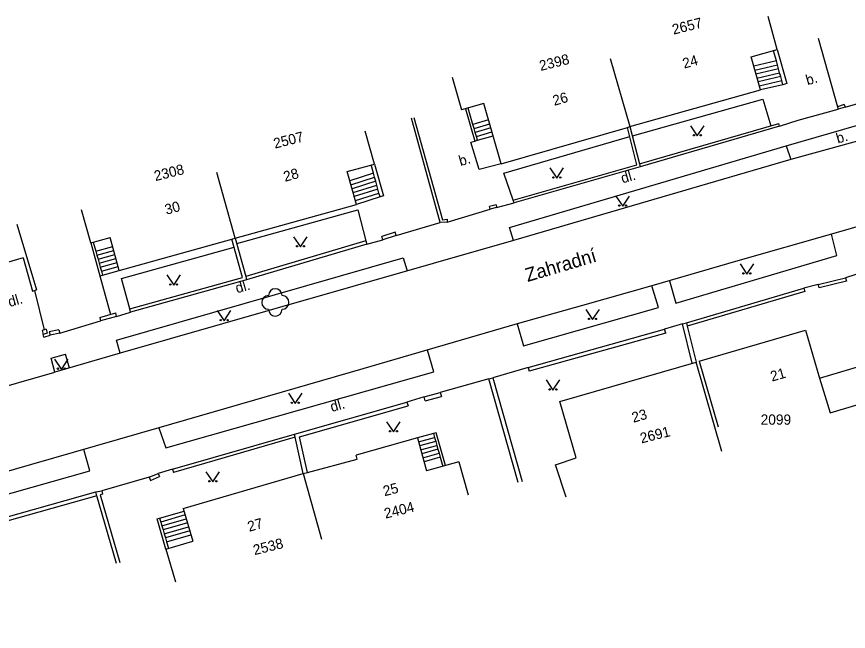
# Model space of a CAD drawing. Extents: x -584400 to -581602, y -1210894 to -1208793.
# Drawn here: x -583100 to -583039.1, y -1209753.8 to -1209708.8 of the extents above; entities that cross this region are included whole.
import ezdxf

# ---------------------------------------------------------------- set-up
doc = ezdxf.new("R2010")
doc.units = 0
for name, color, linetype in [('BUDOVY_MĚŘ', 7, 'Continuous'), ('NÁZVY_ULIC_TOK_SMĚR', 7, 'Continuous'), ('POMOC_POPIS', 7, 'Continuous'), ('ROZHRANÍ_PLOCH', 7, 'Continuous'), ('ZELEŇ', 7, 'Continuous'), ('ZN_DOPLŇKOVÉ', 7, 'Continuous'), ('ZN_KULTUR', 7, 'Continuous'), ('Č_POPIS_EVID', 7, 'Continuous')]:
    doc.layers.add(name, color=color, linetype=linetype)

msp = doc.modelspace()

# ---------------------------------------------------------------- linework, layer by layer
at = {"layer": 'BUDOVY_MĚŘ'}
for points in [[(-583055.11, -1209716.85), (-583045.56, -1209714.16), (-583046.24, -1209711.75), (-583044.32, -1209711.21), (-583044.99, -1209708.8)], [(-583056.55, -1209711.86), (-583055.11, -1209716.85)], [(-583068.14, -1209713.22), (-583067.44, -1209715.62)], [(-583064.53, -1209719.58), (-583065.82, -1209715.15), (-583067.44, -1209715.62)], [(-583064.53, -1209719.58), (-583055.3, -1209716.9), (-583055.11, -1209716.85)], [(-583084.02, -1209725.02), (-583075.14, -1209722.55), (-583075.81, -1209720.14), (-583073.82, -1209719.59), (-583074.49, -1209717.18)], [(-583084.02, -1209725.02), (-583085.36, -1209720.2)], [(-583094.6, -1209725.35), (-583095.27, -1209722.94)], [(-583100.01, -1209723.99), (-583098.56, -1209728.78)], [(-583094.6, -1209725.35), (-583093.18, -1209724.96)], [(-583092.51, -1209727.37), (-583093.18, -1209724.96)], [(-583092.51, -1209727.37), (-583084.26, -1209725.09), (-583084.02, -1209725.02)], [(-583099.55, -1209726.46), (-583104.8, -1209727.98)], [(-583099.55, -1209726.46), (-583098.87, -1209728.88), (-583098.71, -1209728.83), (-583098.56, -1209728.78)], [(-583050.05, -1209734.01), (-583042.26, -1209731.75), (-583041.22, -1209735.26)], [(-583050.05, -1209734.01), (-583048.66, -1209738.81)], [(-583059.77, -1209743.97), (-583060.57, -1209741.6), (-583059.06, -1209741.09), (-583060.24, -1209736.95), (-583050.26, -1209734.08)], [(-583048.38, -1209740.62), (-583050.26, -1209734.08)], [(-583041.22, -1209735.26), (-583037.44, -1209734.13), (-583036.7, -1209736.67)], [(-583041.22, -1209735.26), (-583040.46, -1209737.8), (-583036.7, -1209736.67)], [(-583070.68, -1209739.63), (-583075.16, -1209740.9)], [(-583070.68, -1209739.63), (-583070, -1209742.04)], [(-583079.03, -1209742.23), (-583078.73, -1209742.15), (-583075.08, -1209741.19), (-583075.16, -1209740.9)], [(-583067.63, -1209741.37), (-583070, -1209742.04)], [(-583067.63, -1209741.37), (-583066.95, -1209743.78)], [(-583087.82, -1209744.78), (-583079.03, -1209742.23)], [(-583079.03, -1209742.23), (-583077.69, -1209747.04)], [(-583087.82, -1209744.78), (-583087.12, -1209747.18)], [(-583089.1, -1209747.76), (-583087.12, -1209747.18)], [(-583089.1, -1209747.76), (-583088.4, -1209750.16)]]:
    msp.add_lwpolyline(points, dxfattribs=at)
at = {"layer": 'ROZHRANÍ_PLOCH'}
for points in [[(-583044.39, -1209712.03), (-583044.61, -1209711.29)], [(-583044.32, -1209711.21), (-583043.62, -1209713.7), (-583043.91, -1209713.78)], [(-583044.39, -1209712.03), (-583046.05, -1209712.42)], [(-583044.31, -1209712.32), (-583044.39, -1209712.03)], [(-583045.97, -1209712.71), (-583044.31, -1209712.32)], [(-583044.23, -1209712.61), (-583045.89, -1209713)], [(-583044.23, -1209712.61), (-583044.31, -1209712.32)], [(-583044.15, -1209712.9), (-583044.23, -1209712.61)], [(-583045.81, -1209713.29), (-583044.15, -1209712.9)], [(-583044.07, -1209713.19), (-583045.72, -1209713.58)], [(-583044.07, -1209713.19), (-583044.15, -1209712.9)], [(-583043.99, -1209713.48), (-583044.07, -1209713.19)], [(-583045.64, -1209713.87), (-583043.99, -1209713.48)], [(-583043.91, -1209713.78), (-583045.56, -1209714.16)], [(-583043.91, -1209713.78), (-583043.99, -1209713.48)], [(-583054.93, -1209717.52), (-583045.37, -1209714.83), (-583044.8, -1209716.79)], [(-583005.56, -1209714.6), (-583021.25, -1209719.2), (-583031.75, -1209722.26), (-583035.87, -1209723.43), (-583040.36, -1209724.71)], [(-583067.16, -1209715.54), (-583066.47, -1209717.9)], [(-583066.61, -1209716.7), (-583066.96, -1209715.49)], [(-583065.47, -1209716.36), (-583066.61, -1209716.7)], [(-583043.67, -1209718.26), (-583036.16, -1209716.08)], [(-583066.53, -1209716.98), (-583066.61, -1209716.7)], [(-583066.53, -1209716.98), (-583065.38, -1209716.65)], [(-583066.44, -1209717.27), (-583066.53, -1209716.98)], [(-583065.3, -1209716.94), (-583066.44, -1209717.27)], [(-583066.36, -1209717.56), (-583066.44, -1209717.27)], [(-583066.36, -1209717.56), (-583065.22, -1209717.23)], [(-583066.28, -1209717.85), (-583066.36, -1209717.56)], [(-583066.28, -1209717.85), (-583065.13, -1209717.51)], [(-583063.66, -1209722.22), (-583064.34, -1209720.25), (-583055.13, -1209717.58)], [(-583035.79, -1209717.17), (-583038.99, -1209718.07), (-583043.32, -1209719.26)], [(-583064.53, -1209719.58), (-583066.16, -1209719.98), (-583066.77, -1209717.99), (-583066.47, -1209717.9)], [(-583066.47, -1209717.9), (-583066.28, -1209717.85)], [(-583063.63, -1209725.17), (-583063.92, -1209724.24), (-583043.67, -1209718.26)], [(-583043.67, -1209718.26), (-583043.32, -1209719.26)], [(-583043.32, -1209719.26), (-583052.19, -1209721.84), (-583063.63, -1209725.17)], [(-583073.89, -1209720.26), (-583074.06, -1209719.65)], [(-583073.82, -1209719.59), (-583073.17, -1209721.92), (-583073.41, -1209721.99)], [(-583073.89, -1209720.26), (-583075.62, -1209720.81)], [(-583075.54, -1209721.1), (-583073.81, -1209720.55)], [(-583073.81, -1209720.55), (-583073.89, -1209720.26)], [(-583073.73, -1209720.84), (-583073.81, -1209720.55)], [(-583073.73, -1209720.84), (-583075.46, -1209721.39)], [(-583075.38, -1209721.68), (-583073.65, -1209721.13)], [(-583073.65, -1209721.13), (-583073.73, -1209720.84)], [(-583073.57, -1209721.42), (-583073.65, -1209721.13)], [(-583073.57, -1209721.42), (-583075.3, -1209721.97)], [(-583075.22, -1209722.26), (-583073.49, -1209721.71)], [(-583073.49, -1209721.71), (-583073.57, -1209721.42)], [(-583073.41, -1209721.99), (-583073.49, -1209721.71)], [(-583073.41, -1209721.99), (-583075.14, -1209722.55)], [(-583083.91, -1209725.41), (-583075.03, -1209722.93), (-583074.44, -1209725.21)], [(-583040.36, -1209724.71), (-583047.2, -1209726.68), (-583053.51, -1209728.5)], [(-583052.21, -1209728.13), (-583051.74, -1209729.77), (-583039.95, -1209726.27), (-583040.36, -1209724.71)], [(-583094.6, -1209725.35), (-583093.94, -1209727.76)], [(-583094.41, -1209725.3), (-583094.22, -1209725.97)], [(-583063.63, -1209725.17), (-583081.28, -1209730.23), (-583092.43, -1209733.43)], [(-583094.22, -1209725.97), (-583092.99, -1209725.63)], [(-583094.22, -1209725.97), (-583094.14, -1209726.26)], [(-583094.14, -1209726.26), (-583092.91, -1209725.92)], [(-583091.74, -1209730.19), (-583092.35, -1209727.95), (-583084.1, -1209725.67)], [(-583094.14, -1209726.26), (-583094.06, -1209726.55)], [(-583094.06, -1209726.55), (-583092.83, -1209726.21)], [(-583094.06, -1209726.55), (-583093.98, -1209726.84)], [(-583093.98, -1209726.84), (-583092.75, -1209726.5)], [(-583092.43, -1209733.43), (-583092.7, -1209732.48), (-583071.71, -1209726.46), (-583071.43, -1209727.41)], [(-583093.98, -1209726.84), (-583093.9, -1209727.13)], [(-583093.9, -1209727.13), (-583092.67, -1209726.79)], [(-583093.9, -1209727.13), (-583093.82, -1209727.42)], [(-583093.82, -1209727.42), (-583092.59, -1209727.08)], [(-583093.94, -1209727.76), (-583093.74, -1209727.71)], [(-583093.94, -1209727.76), (-583093.14, -1209730.59)], [(-583093.82, -1209727.42), (-583093.74, -1209727.71)], [(-583093.74, -1209727.71), (-583092.51, -1209727.37)], [(-583053.51, -1209728.5), (-583058.59, -1209729.94), (-583063.36, -1209731.29)], [(-583063.36, -1209731.29), (-583062.91, -1209732.89), (-583053.02, -1209730.08), (-583053.51, -1209728.5)], [(-583063.36, -1209731.29), (-583074.66, -1209734.56), (-583089.61, -1209738.89), (-583089.61, -1209738.9)], [(-583098.02, -1209732.25), (-583098.07, -1209732.05)], [(-583098.02, -1209732.25), (-583097.57, -1209732.11)], [(-583092.43, -1209733.43), (-583097.22, -1209734.81)], [(-583089.61, -1209738.9), (-583089.1, -1209740.35), (-583069.47, -1209734.78), (-583069.93, -1209733.2)], [(-583097.22, -1209734.81), (-583097.49, -1209733.78), (-583096.44, -1209733.5)], [(-583096.16, -1209734.52), (-583096.44, -1209733.5)], [(-583102.69, -1209736.38), (-583097.22, -1209734.81)], [(-583089.61, -1209738.9), (-583098.93, -1209741.57)], [(-583069.5, -1209739.3), (-583070.68, -1209739.63)], [(-583068.63, -1209741.65), (-583069.31, -1209739.25), (-583069.5, -1209739.3)], [(-583069.5, -1209739.3), (-583069.42, -1209739.59)], [(-583070.6, -1209739.92), (-583069.42, -1209739.59)], [(-583069.33, -1209739.88), (-583070.52, -1209740.21)], [(-583069.42, -1209739.59), (-583069.33, -1209739.88)], [(-583069.33, -1209739.88), (-583069.25, -1209740.17)], [(-583160.04, -1209759.32), (-583159.66, -1209760.31), (-583120.2, -1209749.26), (-583094.66, -1209742.04), (-583095.11, -1209740.48)], [(-583070.44, -1209740.5), (-583069.25, -1209740.17)], [(-583069.17, -1209740.46), (-583070.36, -1209740.79)], [(-583070.28, -1209741.08), (-583069.09, -1209740.75)], [(-583069.25, -1209740.17), (-583069.17, -1209740.46)], [(-583069.17, -1209740.46), (-583069.09, -1209740.75)], [(-583069.09, -1209740.75), (-583069.01, -1209741.04)], [(-583069.01, -1209741.04), (-583070.19, -1209741.37)], [(-583069.01, -1209741.04), (-583068.82, -1209741.71)], [(-583098.93, -1209741.58), (-583128.6, -1209750.1), (-583157.29, -1209758.37)], [(-583098.93, -1209741.58), (-583098.93, -1209741.57)], [(-583089.55, -1209745.5), (-583087.76, -1209744.98)], [(-583089.1, -1209747.76), (-583089.74, -1209745.55), (-583089.55, -1209745.5)], [(-583089.55, -1209745.5), (-583089.47, -1209745.78)], [(-583087.68, -1209745.26), (-583089.47, -1209745.78)], [(-583089.38, -1209746.07), (-583087.6, -1209745.55)], [(-583089.47, -1209745.78), (-583089.38, -1209746.07)], [(-583089.38, -1209746.07), (-583089.3, -1209746.36)], [(-583087.51, -1209745.84), (-583089.3, -1209746.36)], [(-583089.22, -1209746.65), (-583087.43, -1209746.13)], [(-583089.3, -1209746.36), (-583089.22, -1209746.65)], [(-583089.22, -1209746.65), (-583089.13, -1209746.94)], [(-583087.34, -1209746.42), (-583089.13, -1209746.94)], [(-583089.05, -1209747.23), (-583087.26, -1209746.71)], [(-583089.13, -1209746.94), (-583089.05, -1209747.23)], [(-583089.05, -1209747.23), (-583088.91, -1209747.7)]]:
    msp.add_lwpolyline(points, dxfattribs=at)
at = {"layer": 'ZELEŇ'}
msp.add_circle((-583081.08, -1209729.71), 0.0005, dxfattribs=at)
for centre, start, end in [((-583081.08, -1209729.21), 0, 179.99999), ((-583081.58, -1209729.71), 89.99999, 269.99999), ((-583080.58, -1209729.71), 270, 89.99999), ((-583081.08, -1209730.21), 179.99999, 359.99999)]:
    msp.add_arc(centre, 0.5, start, end, dxfattribs=at)
at = {"layer": 'ZN_DOPLŇKOVÉ'}
for points in [[(-583041.33, -1209710.37), (-583039.92, -1209715.39)], [(-583039.36, -1209715.42), (-583036.58, -1209714.61)], [(-583042.8, -1209716.38), (-583039.87, -1209715.58)], [(-583039.42, -1209715.23), (-583039.92, -1209715.39)], [(-583039.92, -1209715.39), (-583039.87, -1209715.58)], [(-583039.42, -1209715.23), (-583039.36, -1209715.42), (-583039.87, -1209715.58)], [(-583068.5, -1209723.63), (-583068.49, -1209723.83), (-583069, -1209723.87), (-583071.12, -1209716.24)], [(-583070.93, -1209716.19), (-583068.85, -1209723.66), (-583068.5, -1209723.63)], [(-583044.16, -1209716.81), (-583042.8, -1209716.38)], [(-583063.66, -1209722.22), (-583054.6, -1209719.64), (-583055.3, -1209716.9)], [(-583055.11, -1209716.85), (-583054.41, -1209719.58)], [(-583054.41, -1209719.58), (-583044.22, -1209716.62)], [(-583044.16, -1209716.81), (-583054.36, -1209719.78)], [(-583044.16, -1209716.81), (-583044.22, -1209716.62)], [(-583054.41, -1209719.58), (-583054.36, -1209719.78), (-583063.6, -1209722.42), (-583063.66, -1209722.22)], [(-583064.88, -1209722.77), (-583063.6, -1209722.42)], [(-583068.49, -1209723.83), (-583065.34, -1209722.88)], [(-583064.92, -1209722.58), (-583064.88, -1209722.77), (-583065.34, -1209722.88), (-583065.39, -1209722.69)], [(-583064.92, -1209722.58), (-583065.39, -1209722.69)], [(-583072.23, -1209724.81), (-583069, -1209723.87)], [(-583072.23, -1209724.81), (-583072.31, -1209724.57), (-583073.29, -1209724.89)], [(-583072.23, -1209724.81), (-583073.21, -1209725.13), (-583073.29, -1209724.89)], [(-583091.74, -1209730.19), (-583083.49, -1209727.88), (-583084.26, -1209725.09)], [(-583084.02, -1209725.02), (-583083.25, -1209727.82)], [(-583074.44, -1209725.21), (-583083.25, -1209727.82)], [(-583074.44, -1209725.21), (-583074.37, -1209725.45), (-583083.18, -1209728.06)], [(-583074.37, -1209725.45), (-583073.21, -1209725.13)], [(-583036.67, -1209727.05), (-583039.32, -1209727.92)], [(-583083.25, -1209727.82), (-583083.18, -1209728.06), (-583091.68, -1209730.43), (-583091.74, -1209730.19)], [(-583041.26, -1209728.64), (-583041.32, -1209728.4), (-583039.32, -1209727.92), (-583039.26, -1209728.16)], [(-583041.32, -1209728.4), (-583042.39, -1209728.68)], [(-583039.26, -1209728.16), (-583041.26, -1209728.64)], [(-583098.71, -1209728.83), (-583098.01, -1209731.72)], [(-583050.97, -1209731.21), (-583042.39, -1209728.68), (-583042.31, -1209728.92)], [(-583042.31, -1209728.92), (-583050.91, -1209731.46)], [(-583093.94, -1209730.81), (-583092.77, -1209730.48)], [(-583093.94, -1209730.81), (-583093.87, -1209731.05)], [(-583092.7, -1209730.73), (-583093.87, -1209731.05)], [(-583092.7, -1209730.73), (-583092.77, -1209730.48)], [(-583092.7, -1209730.73), (-583091.68, -1209730.43)], [(-583096.86, -1209731.95), (-583093.87, -1209731.05)], [(-583051.26, -1209731.28), (-583052.57, -1209731.66)], [(-583051.26, -1209731.28), (-583050.97, -1209731.21)], [(-583050.55, -1209734.15), (-583051.26, -1209731.28)], [(-583050.97, -1209731.21), (-583050.91, -1209731.46)], [(-583050.91, -1209731.46), (-583050.26, -1209734.08)], [(-583098.01, -1209731.72), (-583098.15, -1209731.76), (-583098.07, -1209732.05)], [(-583097.86, -1209731.68), (-583097.78, -1209731.97), (-583098.07, -1209732.05)], [(-583097.86, -1209731.68), (-583098.01, -1209731.72)], [(-583096.93, -1209731.71), (-583097.64, -1209731.87), (-583097.57, -1209732.11)], [(-583096.93, -1209731.71), (-583096.86, -1209731.95), (-583097.57, -1209732.11)], [(-583062.56, -1209734.47), (-583052.57, -1209731.66)], [(-583052.49, -1209731.95), (-583062.48, -1209734.75)], [(-583052.49, -1209731.95), (-583052.57, -1209731.66)], [(-583062.56, -1209734.47), (-583065.15, -1209735.23)], [(-583062.56, -1209734.47), (-583062.48, -1209734.75)], [(-583063.3, -1209742.9), (-583065.44, -1209735.31), (-583065.15, -1209735.23)], [(-583065.15, -1209735.23), (-583063.01, -1209742.82)], [(-583065.44, -1209735.31), (-583069, -1209736.31)], [(-583070.1, -1209736.91), (-583070.18, -1209736.62), (-583069, -1209736.31), (-583068.92, -1209736.6)], [(-583079.62, -1209739.58), (-583079.67, -1209739.34), (-583071.45, -1209737), (-583071.36, -1209737.28)], [(-583070.18, -1209736.62), (-583071.45, -1209737)], [(-583070.1, -1209736.91), (-583068.92, -1209736.6)], [(-583078.73, -1209742.15), (-583079.32, -1209739.55), (-583071.36, -1209737.28)], [(-583088.6, -1209741.92), (-583079.67, -1209739.34)], [(-583079.62, -1209739.58), (-583088.53, -1209742.16)], [(-583079.03, -1209742.23), (-583079.62, -1209739.58)], [(-583088.6, -1209741.92), (-583089.67, -1209742.22)], [(-583088.6, -1209741.92), (-583088.53, -1209742.16)], [(-583090.33, -1209742.51), (-583093.78, -1209743.5)], [(-583090.33, -1209742.51), (-583089.67, -1209742.22), (-583089.56, -1209742.45)], [(-583090.33, -1209742.51), (-583090.22, -1209742.74), (-583089.56, -1209742.45)], [(-583135.31, -1209755.17), (-583118.62, -1209750.44), (-583094.23, -1209743.57)], [(-583094.15, -1209743.86), (-583094.23, -1209743.57), (-583093.78, -1209743.5), (-583093.74, -1209743.75)], [(-583093.74, -1209743.75), (-583093.91, -1209743.78), (-583092.47, -1209748.74)], [(-583094.15, -1209743.86), (-583118.53, -1209750.73), (-583135.23, -1209755.46)], [(-583092.71, -1209748.81), (-583094.15, -1209743.86)]]:
    msp.add_lwpolyline(points, dxfattribs=at)
at = {"layer": 'ZN_KULTUR'}
for points in [[(-583050.68, -1209716.78), (-583050.18, -1209717.53), (-583049.68, -1209716.78)], [(-583060.97, -1209719.87), (-583060.47, -1209720.62), (-583059.97, -1209719.87)], [(-583056.14, -1209721.93), (-583055.64, -1209722.68), (-583055.14, -1209721.93)], [(-583079.74, -1209724.9), (-583079.24, -1209725.65), (-583078.74, -1209724.9)], [(-583047.05, -1209726.89), (-583046.55, -1209727.64), (-583046.05, -1209726.89)], [(-583089.02, -1209727.7), (-583088.52, -1209728.45), (-583088.02, -1209727.7)], [(-583085.33, -1209730.31), (-583084.83, -1209731.06), (-583084.33, -1209730.31)], [(-583058.35, -1209730.22), (-583057.85, -1209730.97), (-583057.35, -1209730.22)], [(-583097.25, -1209733.86), (-583096.75, -1209734.61), (-583096.25, -1209733.86)], [(-583061.25, -1209735.38), (-583060.75, -1209736.13), (-583060.25, -1209735.38)], [(-583080.12, -1209736.35), (-583079.62, -1209737.1), (-583079.12, -1209736.35)], [(-583072.93, -1209738.44), (-583072.43, -1209739.19), (-583071.93, -1209738.44)], [(-583086.16, -1209742.1), (-583085.66, -1209742.85), (-583085.16, -1209742.1)]]:
    msp.add_lwpolyline(points, dxfattribs=at)
for centre in [(-583050.43, -1209717.48), (-583049.93, -1209717.48), (-583060.72, -1209720.57), (-583060.22, -1209720.57), (-583055.89, -1209722.63), (-583055.39, -1209722.63), (-583079.49, -1209725.6), (-583078.99, -1209725.6), (-583046.8, -1209727.59), (-583046.3, -1209727.59), (-583088.77, -1209728.4), (-583088.27, -1209728.4), (-583085.08, -1209731.01), (-583084.58, -1209731.01), (-583058.1, -1209730.92), (-583057.6, -1209730.92), (-583097, -1209734.56), (-583096.5, -1209734.56), (-583061, -1209736.08), (-583060.5, -1209736.08), (-583079.87, -1209737.05), (-583079.37, -1209737.05), (-583072.68, -1209739.14), (-583072.18, -1209739.14), (-583085.91, -1209742.8), (-583085.41, -1209742.8)]:
    msp.add_circle(centre, 0.05, dxfattribs=at)

# ---------------------------------------------------------------- texts
at = {"layer": 'NÁZVY_ULIC_TOK_SMĚR'}
msp.add_text('Zahradní', height=1, rotation=16.46274, dxfattribs=at).set_placement((-583062.61, -1209728.22))
at = {"layer": 'POMOC_POPIS'}
for s, rotation, p in [('b.', 16.16423, (-583042.11, -1209713.83)), ('b.', 16.16423, (-583039.89, -1209718.09)), ('b.', 16.16423, (-583067.52, -1209719.74)), ('dl.', 16.16423, (-583055.65, -1209721.01)), ('dl.', 16.16423, (-583083.88, -1209729.05)), (' dl.', 16.14435, (-583100.8, -1209730.13)), ('dl.', 15.84584, (-583076.94, -1209737.73))]:
    msp.add_text(s, height=0.75, rotation=rotation, dxfattribs=at).set_placement(p)
at = {"layer": 'Č_POPIS_EVID'}
for s, rotation, p in [('2657', 13.99186, (-583051.92, -1209710.12)), ('2398', 13.99186, (-583061.65, -1209712.78)), ('24', 15.72391, (-583051.14, -1209712.61)), ('26', 16.16423, (-583060.65, -1209715.33)), ('2507', 13.99186, (-583081.11, -1209718.46)), ('2308', 13.99186, (-583089.86, -1209720.84)), ('28', 15.56136, (-583080.37, -1209720.89)), ('30', 15.44505, (-583089.06, -1209723.3)), ('21', 16.06218, (-583044.71, -1209735.51)), ('23', 16.06218, (-583054.86, -1209738.52)), ('2691', 13.99186, (-583054.27, -1209740.03)), ('25', 14.71424, (-583073.08, -1209743.9)), ('2404', 13.99186, (-583073.01, -1209745.54)), ('27', 16.2084, (-583082.99, -1209746.5)), ('2538', 13.99186, (-583082.6, -1209748.21))]:
    msp.add_text(s, height=0.75, rotation=rotation, dxfattribs=at).set_placement(p)
msp.add_text('2099', height=0.75, dxfattribs=at).set_placement((-583045.54, -1209738.66))

doc.saveas('drawing.dxf')
